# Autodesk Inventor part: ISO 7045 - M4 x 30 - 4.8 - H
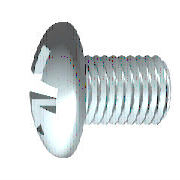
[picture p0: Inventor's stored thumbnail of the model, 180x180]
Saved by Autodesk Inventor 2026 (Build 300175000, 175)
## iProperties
Created: 2013-02
Part Number: ISO 7045 - M4 x 30 - 4.8 - H
Material: Stainless Steel, 440C
Description: Pan head screw with type H cross recess - product grade A
Document SubType Name: Modeling
Standard: ISO 7045
Designer: Cadskolen
Standard Revision: Second edition 1994-04-01
Standards Organization: ISO
Language: en-US
Size Designation: M4 x 30 - 4.8 - H
Categories: <MemberInstance><Categories><Category DisplayName="Fasteners" InternalName="e4da775c-781d-43d5-af7c-5136215cf5a6" Mnemonic="FSTN"><Category DisplayName="Bolts"
Density: 7.75 g/cm^3
Appearance: Semi-Polished
IsCustomPart: 0
Author: Cadskolen
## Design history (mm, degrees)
workplane "Work Plane3"
sketch "Sketch2"
  geometry: L1 (-5.513, 0)-(5.513, 0) reference; L2 (0, -5.513)-(0, 5.513) reference; L3 (0, 2.2)-(0, 0); L4 (0, 0)-(2.2, 0); L5 (0, 0)-(2.785, 2.785); L6 (0.415, 2.161)-(0.386, 0.666); L7 (2.161, 0.415)-(0.666, 0.386); L8 (0.415, -2.161)-(0.386, -0.666); L9 (2.161, -0.415)-(0.666, -0.386); L10 (-0.415, 2.161)-(-0.386, 0.666); L11 (-2.161, 0.415)-(-0.666, 0.386); L12 (-2.161, -0.415)-(-0.666, -0.386); L13 (-0.415, -2.161)-(-0.386, -0.666); A1 r 0.66 centre (0, 0) between (0.66, 0) and (0, 0.66); A2 r 2.2 centre (0, 0) between (2.2, 0) and (2.161, 0.415); A3 r 2.2 centre (0, 0) between (0.415, 2.161) and (0, 2.2); A4 r 2.2 centre (0, 0) between (2.161, 0.415) and (0.415, 2.161); A5 r 2.2 centre (0, 0) between (0, -2.2) and (0.415, -2.161); A6 r 2.2 centre (0, 0) between (0.415, -2.161) and (2.161, -0.415); A7 r 2.2 centre (0, 0) between (2.161, -0.415) and (2.2, 0); A8 r 2.2 centre (0, 0) between (-2.161, 0.415) and (-2.2, 0); A9 r 2.2 centre (0, 0) between (-0.415, 2.161) and (-2.161, 0.415); A10 r 2.2 centre (0, 0) between (0, 2.2) and (-0.415, 2.161); A11 r 2.2 centre (0, 0) between (-2.2, 0) and (-2.161, -0.415); A12 r 2.2 centre (0, 0) between (-2.161, -0.415) and (-0.415, -2.161); A13 r 2.2 centre (0, 0) between (-0.415, -2.161) and (0, -2.2); A14 r 0.77 centre (0, 0) between (0.77, 0) and (0, 0.77); A15 r 0.275 centre (0.661, 0.661) between (0.386, 0.666) and (0.666, 0.386); A16 r 0.275 centre (0.661, -0.661) between (0.666, -0.386) and (0.386, -0.666); A17 r 0.275 centre (-0.661, 0.661) between (-0.666, 0.386) and (-0.386, 0.666); A18 r 0.275 centre (-0.661, -0.661) between (-0.386, -0.666) and (-0.666, -0.386); 1 further point
  constraints: 38 point on circle, 22 end point, 19 symmetric about line, 18 centre point, 4 coincident, 3 collinear, 3 point on line, 3 tangent, 1 perpendicular, 21 other
  dimensions: "d4" = 45 deg angle of L5 L4; "d5" = 1.32 diameter of A1 (= 0.3 x SDM); "d6" = 4.4 diameter of A4 (= SDM); "d7" = 0.415 distance from line of L6.start L3 (= 0.5 x SBR); "d14" = 1.54 diameter of A14 (= 0.35 x SDM)
extrude "Slot" join sketch "Sketch2" taper "d15" = 5 deg; stored distance "d54" = 10
revolve "Cut" stored, may be unused: angle "d56" = 90 deg
revolve "Body" stored, may be unused: angle "d18" = 90 deg
body "Solid1"
sketch "Sketch1"
  geometry: L1 (30, 0)-(30, 2); L2 (30, 2)-(1.4, 2); L3 (3.962, 5.08)-(3.962, 5.08); L4 (-3.1, 0)-(-3.1, 3.892); L5 (-2.773, 2.037)-(-1.426, 1.365); L6 (-1.426, 1.365)-(-0.7, 0); L7 (-0.7, 0)-(30, 0); L8 (-10.108, 0)-(36.685, 0) reference; L9 (0, -1.016)-(0, 6.096) reference; L10 (-2.773, 2.037)-(-3.1, 2.2); L11 (-1.771, 3.938)-(-3.1, 3.892); L12 (-1.771, 3.938)-(0, 4); L13 (0, 4)-(0, 1.811); L14 (0, 1.811)-(0.971, 1.811); L15 (0.971, 1.811)-(1.4, 2); L16 (1.4, 2)-(0, 2); A1 r 6.5 centre (3.4, 0) between (-1.771, 3.938) and (-3.1, 0)
  constraints: 28 end point, 5 point on line, 4 collinear, 4 point on circle, 3 parallel, 2 perpendicular, 1 centre point, 1 horizontal, 1 tangent
  dimensions: "d1" = 4 diameter of L2 L7 (= GD); "d2" = 2.4 distance from line of L6.end L4 (= STI); "d11" = 4.4 diameter of L10.end L7 (= SDM); "d12" = 62 deg angle of L6 L7; "d13" = 26.5 deg angle of L5 L7; "d17" = 8 diameter of L12.end L7 (= KOD); "d19" = 2 deg angle of L12 L7 (= KEWI); "d20" = 3.1 distance between parallel lines of L4 L13 (= KOH); "d21" = 6.5 radius of A1 (= KR); "d23" = 3.62111 diameter of L14 L7 (= BDM); "d24" = 28.6 distance of L1.end L2.end (= GEL); "d25" = 0.42941 horizontal distance of L14.end L2.end (= GAL); "d28" = 30 distance between parallel lines of L1 L13 (= NLG)
workplane "Work Plane1"
fillet "Fillet1" dims "d29" = 1.3 (= RR)
fillet "Fillet2" dims "d16" = 0.166 (= 0.2 x SBR)
feature "Thread" dims "d8" = 28.6 (= GEL), "d9" = 0
chamfer "Chamfer1" distance "d26" = 0.42941 (= -0.5 x SPD + 0.5 x GD); stored, may be unused: second distance "d27" = 0.42952 (computed from GUL), angle "d78" = 45 deg
other parameters: "GD" = 4 [user parameter; used in 2 equation terms], "NLG" = 30 [user parameter; used in 1 equation term], "GEL" = 28.6 [user parameter; used in 2 equation terms], "KOD" = 8 [user parameter; used in 1 equation term], "KOH" = 3.1 [user parameter; used in 2 equation terms], "SDM" = 4.4 [user parameter; used in 4 equation terms], "STI" = 2.4 [user parameter; used in 1 equation term], "SBR" = 0.83 [user parameter; used in 2 equation terms], "GAL" = 0.42941 (= 0.61345 x PTC) [user parameter; used in 1 equation term], "SPD" = 3.14117 (= NND - 1.2269 x PTC) [user parameter; used in 1 equation term], "KEWI" = 2 deg [user parameter; used in 1 equation term], "d3" = -3.1 (= -KOH), "KR" = 6.5 [user parameter; used in 1 equation term], "BDM" = 3.62111 [user parameter; used in 1 equation term], "GUL" = 0.42941 (= 0.61345 x PTC) [user parameter; used in 1 equation term], "RR" = 1.3 [user parameter; used in 1 equation term], "PTC" = 0.7 [user parameter; used in 5 equation terms], "THREADDIA" = 4 [user parameter; used in 1 equation term], "TOA" = 30 deg [user parameter], "TPU" = 14.28571 (computed from PTC) [user parameter], "NND" = 4 [user parameter; used in 1 equation term], "GD1" = 3.14117 (= THREADDIA - 1.2269 x PTC) [user parameter]
